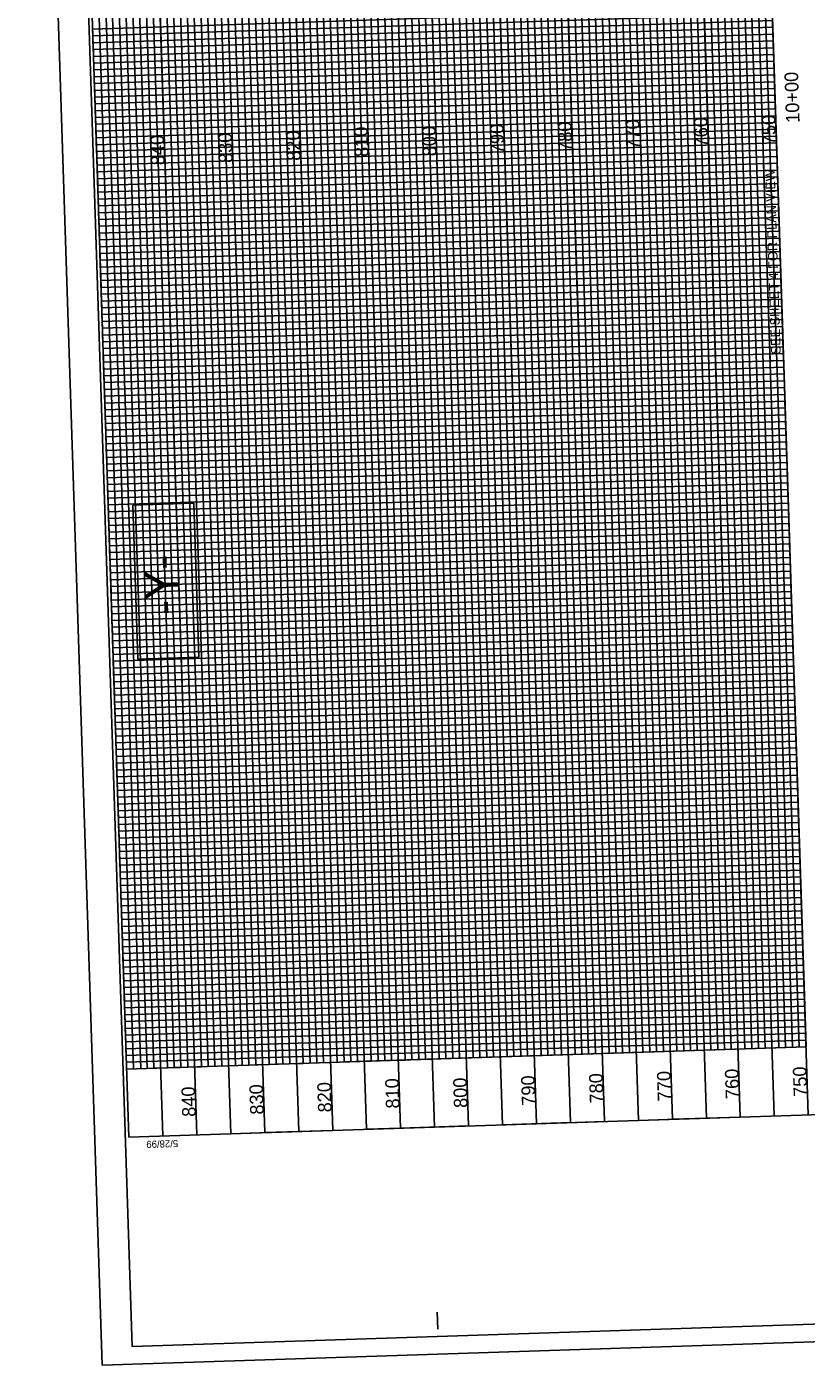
# Model space of a CAD drawing. Extents: x 1627314 to 1628469, y 762309 to 764230.
# Drawn here: x 1627314 to 1627888, y 762309 to 763293 of the extents above; entities that cross this region are included whole.
import ezdxf

# ---------------------------------------------------------------- set-up
doc = ezdxf.new("R2010")
doc.units = 0
for name, color, linetype in [('Exist Vertical Profile Horizontal Axis Label Major', 7, 'Continuous'), ('Exist Vertical Profile Vertical Axis Label', 7, 'Continuous'), ('Prop DSN Text', 7, 'Continuous'), ('Prop Grid Mask', 7, 'Continuous'), ('Sheet Data Field CELL', 7, 'Continuous'), ('Sheet DOT Grid CELL', 7, 'Continuous'), ('Sheet Layout Profile Border Port 1', 7, 'Continuous'), ('Sheet Plot Border Inside CELL', 7, 'Continuous'), ('Sheet Plot Border Outside CELL', 7, 'Continuous'), ('Sheet Profile CELL', 7, 'Continuous'), ('Sheet Profile Grid Major CELL', 7, 'Continuous'), ('Sheet Profile Grid Middle CELL', 7, 'Continuous'), ('Sheet Profile Grid Minor CELL', 7, 'Continuous')]:
    doc.layers.add(name, color=color, linetype=linetype)

msp = doc.modelspace()

# ---------------------------------------------------------------- linework, layer by layer
at = {"layer": 'Prop Grid Mask'}
for points in [[(1627366.44, 763176.67), (1627364.8, 763226.64), (1627864.53, 763242.99), (1627866.17, 763193.01)], [(1627856.17, 763192.69), (1627860.92, 763047.76), (1627870.91, 763048.09), (1627866.17, 763193.01)], [(1627440.71, 762829.99), (1627437.01, 762943.01), (1627392.29, 762941.55), (1627395.99, 762828.53)]]:
    msp.add_lwpolyline(points, close=True, dxfattribs=at)
at = {"layer": 'Sheet DOT Grid CELL'}
for p, q in [((1627590.15, 763984.41), (1627639.19, 762485.21)), ((1627640.12, 763986.05), (1627689.16, 762486.85)), ((1627690.1, 763987.68), (1627739.13, 762488.48)), ((1627740.07, 763989.32), (1627789.11, 762490.12)), ((1627790.04, 763990.95), (1627839.08, 762491.75)), ((1627396.8, 763777.93), (1627439.29, 762478.68)), ((1627446.77, 763779.57), (1627489.27, 762480.31)), ((1627496.74, 763781.25), (1627539.24, 762481.95)), ((1627546.72, 763782.83), (1627589.21, 762483.58)), ((1627862.9, 763292.96), (1627363.17, 763276.61)), ((1627864.53, 763242.99), (1627364.8, 763226.64)), ((1627866.17, 763193.01), (1627366.44, 763176.67)), ((1627867.8, 763143.04), (1627368.07, 763126.69)), ((1627869.44, 763093.07), (1627369.71, 763076.72)), ((1627871.07, 763043.09), (1627371.34, 763026.75)), ((1627872.71, 762993.12), (1627372.98, 762976.77)), ((1627874.34, 762943.15), (1627374.61, 762926.8)), ((1627875.98, 762893.17), (1627376.24, 762876.83)), ((1627877.61, 762843.2), (1627377.88, 762826.85)), ((1627879.25, 762793.23), (1627379.51, 762776.88)), ((1627880.88, 762743.25), (1627381.15, 762726.91)), ((1627882.52, 762693.28), (1627382.78, 762676.93)), ((1627884.15, 762643.31), (1627384.42, 762626.96)), ((1627885.78, 762593.33), (1627386.05, 762576.99)), ((1627887.42, 762543.36), (1627387.69, 762527.01))]:
    msp.add_line(p, q, dxfattribs=at)
at = {"layer": 'Sheet Layout Profile Border Port 1'}
msp.add_lwpolyline([(1627548.65, 762532.28), (1627887.42, 762543.36), (1627841.65, 763942.61), (1627566.8, 763933.62)], dxfattribs=at)
at = {"layer": 'Sheet Plot Border Inside CELL'}
msp.add_lwpolyline([(1628446.34, 762357.53), (1628391.86, 764023.14), (1627337.33, 763988.65), (1627391.81, 762323.04)], close=True, dxfattribs=at)
at = {"layer": 'Sheet Plot Border Outside CELL'}
msp.add_lwpolyline([(1628469.21, 762345.27), (1628413.63, 764044.37), (1627314.22, 764008.4), (1627369.79, 762309.31)], close=True, dxfattribs=at)
at = {"layer": 'Sheet Profile CELL'}
for p, q in [((1627889.05, 762493.39), (1627840.02, 763992.59)), ((1627616.56, 762335.89), (1627616.15, 762348.39))]:
    msp.add_line(p, q, dxfattribs=at)
msp.add_lwpolyline([(1627340.28, 763976.24), (1627389.32, 762477.04), (1628438.76, 762511.37), (1628389.72, 764010.57)], close=True, dxfattribs=at)
at = {"layer": 'Sheet Profile Grid Major CELL'}
for points in [[(1627546.71, 763782.88), (1627589.21, 762483.58), (1627639.19, 762485.21), (1627590.15, 763984.41)], [(1627640.12, 763986.05), (1627689.16, 762486.85), (1627739.13, 762488.48), (1627690.1, 763987.68)], [(1627740.07, 763989.32), (1627789.11, 762490.12), (1627789.11, 762490.12), (1627839.08, 762491.75), (1627790.04, 763990.95)], [(1627439.29, 762478.68), (1627396.79, 763777.98)], [(1627446.77, 763779.62), (1627489.27, 762480.31), (1627539.24, 762481.95), (1627496.74, 763781.25)], [(1627387.69, 762527.01), (1627887.42, 762543.36), (1627885.78, 762593.33), (1627386.05, 762576.99), (1627384.42, 762626.96), (1627884.15, 762643.31), (1627882.52, 762693.28), (1627382.78, 762676.93), (1627381.15, 762726.91), (1627880.88, 762743.25), (1627879.25, 762793.23), (1627379.51, 762776.88), (1627377.88, 762826.85), (1627877.61, 762843.2), (1627875.98, 762893.17), (1627376.24, 762876.83), (1627374.61, 762926.8), (1627874.34, 762943.15), (1627872.71, 762993.12), (1627372.98, 762976.77), (1627371.34, 763026.75), (1627871.07, 763043.09), (1627869.44, 763093.07), (1627369.71, 763076.72), (1627368.07, 763126.69), (1627867.8, 763143.04), (1627866.17, 763193.01), (1627366.44, 763176.67), (1627364.8, 763226.64), (1627864.53, 763242.99), (1627862.9, 763292.96), (1627363.17, 763276.61), (1627361.53, 763326.59)]]:
    msp.add_lwpolyline(points, dxfattribs=at)
at = {"layer": 'Sheet Profile Grid Middle CELL'}
msp.add_line((1627414.31, 762477.86), (1627371.81, 763777.11), dxfattribs=at)
for points in [[(1627815.03, 763991.77), (1627864.07, 762492.57)], [(1627615.14, 763985.23), (1627664.17, 762486.03), (1627714.15, 762487.67), (1627665.11, 763986.86)], [(1627715.08, 763988.5), (1627764.12, 762489.3), (1627814.09, 762490.94), (1627765.06, 763990.13)], [(1627521.73, 763782.02), (1627564.23, 762482.76), (1627614.2, 762484.4), (1627570.88, 763808.69)], [(1627421.78, 763778.8), (1627464.28, 762479.49), (1627514.25, 762481.13), (1627471.75, 763780.43)], [(1627386.87, 762552), (1627886.6, 762568.35), (1627884.97, 762618.32), (1627385.23, 762601.97), (1627383.6, 762651.95), (1627883.33, 762668.29), (1627881.7, 762718.27), (1627381.97, 762701.92), (1627380.33, 762751.89), (1627880.06, 762768.24), (1627878.43, 762818.21), (1627378.7, 762801.87), (1627377.06, 762851.84), (1627876.79, 762868.19), (1627875.16, 762918.16), (1627375.43, 762901.81), (1627373.79, 762951.79), (1627873.53, 762968.13), (1627871.89, 763018.11), (1627372.16, 763001.76), (1627370.52, 763051.73), (1627870.26, 763068.08), (1627868.62, 763118.05), (1627868.62, 763118.05), (1627368.89, 763101.71), (1627367.25, 763151.68), (1627866.99, 763168.03), (1627865.35, 763218), (1627365.62, 763201.65), (1627363.98, 763251.63), (1627863.72, 763267.97), (1627862.08, 763317.95)]]:
    msp.add_lwpolyline(points, dxfattribs=at)
at = {"layer": 'Sheet Profile Grid Minor CELL'}
for p, q in [((1627867.43, 762542.71), (1627821.66, 763941.96)), ((1627826.66, 763942.12), (1627872.43, 762542.87)), ((1627877.42, 762543.03), (1627831.66, 763942.29)), ((1627576.79, 763933.95), (1627622.56, 762534.7)), ((1627627.56, 762534.86), (1627581.79, 763934.11)), ((1627586.79, 763934.28), (1627632.56, 762535.02)), ((1627642.55, 762535.35), (1627596.78, 763934.6)), ((1627601.78, 763934.77), (1627647.55, 762535.51)), ((1627652.55, 762535.68), (1627606.78, 763934.93)), ((1627611.77, 763935.09), (1627657.54, 762535.84)), ((1627667.54, 762536.17), (1627621.77, 763935.42)), ((1627626.77, 763935.58), (1627672.53, 762536.33)), ((1627677.53, 762536.5), (1627631.76, 763935.75)), ((1627636.76, 763935.91), (1627682.53, 762536.66)), ((1627692.52, 762536.99), (1627646.75, 763936.24)), ((1627651.75, 763936.4), (1627697.52, 762537.15)), ((1627702.52, 762537.31), (1627656.75, 763936.56)), ((1627661.75, 763936.73), (1627707.52, 762537.48)), ((1627717.51, 762537.8), (1627671.74, 763937.05)), ((1627676.74, 763937.22), (1627722.51, 762537.97)), ((1627727.51, 762538.13), (1627681.74, 763937.38)), ((1627686.73, 763937.55), (1627732.5, 762538.29)), ((1627742.5, 762538.62), (1627696.73, 763937.87)), ((1627701.73, 763938.04), (1627747.49, 762538.78)), ((1627752.49, 762538.95), (1627706.72, 763938.2)), ((1627711.72, 763938.36), (1627757.49, 762539.11)), ((1627767.48, 762539.44), (1627721.71, 763938.69)), ((1627726.71, 763938.85), (1627772.48, 762539.6)), ((1627731.71, 763939.02), (1627777.48, 762539.76)), ((1627736.71, 763939.18), (1627782.48, 762539.93)), ((1627792.47, 762540.25), (1627746.7, 763939.51)), ((1627751.7, 763939.67), (1627797.47, 762540.42)), ((1627802.47, 762540.58), (1627756.7, 763939.83)), ((1627761.69, 763940), (1627807.46, 762540.75)), ((1627817.46, 762541.07), (1627771.69, 763940.32)), ((1627776.69, 763940.49), (1627822.45, 762541.24)), ((1627827.45, 762541.4), (1627781.68, 763940.65)), ((1627786.68, 763940.81), (1627832.45, 762541.56)), ((1627842.44, 762541.89), (1627796.67, 763941.14)), ((1627801.67, 763941.3), (1627847.44, 762542.05)), ((1627852.44, 762542.22), (1627806.67, 763941.47)), ((1627811.67, 763941.63), (1627857.44, 762542.38)), ((1627392.68, 762527.18), (1627351.82, 763776.51)), ((1627356.82, 763776.67), (1627398.03, 762527.35)), ((1627402.68, 762527.5), (1627361.81, 763776.84)), ((1627481.75, 763780.71), (1627522.61, 762531.43)), ((1627486.75, 763780.92), (1627527.61, 762531.59)), ((1627491.74, 763781.09), (1627532.61, 762531.75)), ((1627542.6, 762532.08), (1627501.74, 763781.41)), ((1627506.74, 763781.58), (1627547.6, 762532.25)), ((1627552.6, 762532.41), (1627511.73, 763781.69)), ((1627531.72, 763782.34), (1627572.59, 762533.06)), ((1627577.59, 762533.23), (1627536.72, 763782.51)), ((1627556.71, 763783.16), (1627597.57, 762533.88)), ((1627602.57, 762534.04), (1627561.71, 763783.33)), ((1627397.68, 762527.34), (1627397.68, 762527.34))]:
    msp.add_line(p, q, dxfattribs=at)
for points in [[(1627836.65, 763942.45), (1627882.42, 762543.2)], [(1627566.71, 763783.49), (1627607.57, 762534.21), (1627617.56, 762534.53), (1627571.79, 763933.79)], [(1627366.81, 763777), (1627407.68, 762527.67), (1627417.67, 762528), (1627376.81, 763777.33)], [(1627381.8, 763777.44), (1627422.67, 762528.16), (1627427.67, 762528.32), (1627386.8, 763777.65)], [(1627391.8, 763777.82), (1627432.66, 762528.49), (1627442.66, 762528.81), (1627401.79, 763778.14)], [(1627406.79, 763778.31), (1627447.65, 762528.98), (1627452.65, 762529.14), (1627411.79, 763778.47)], [(1627416.78, 763778.63), (1627457.65, 762529.3), (1627467.64, 762529.63), (1627426.78, 763778.96)], [(1627431.78, 763779.13), (1627472.64, 762529.79), (1627477.64, 762529.96), (1627436.77, 763779.29)], [(1627441.77, 763779.45), (1627482.64, 762530.12), (1627492.63, 762530.45), (1627451.77, 763779.78)], [(1627456.86, 763779.95), (1627497.72, 762530.71), (1627502.62, 762530.87), (1627461.76, 763780.11)], [(1627466.76, 763780.27), (1627507.62, 762530.94), (1627517.62, 762531.26), (1627476.75, 763780.6)], [(1627516.73, 763781.85), (1627557.6, 762532.57), (1627567.59, 762532.9), (1627526.73, 763782.18)], [(1627541.72, 763782.67), (1627582.58, 762533.39), (1627592.58, 762533.72), (1627551.71, 763783)], [(1627862.57, 763302.95), (1627362.84, 763286.61), (1627362.68, 763291.61), (1627862.41, 763307.95)], [(1627370.36, 763056.73), (1627870.09, 763073.08), (1627869.93, 763078.07), (1627370.2, 763061.73), (1627370.03, 763066.73), (1627869.77, 763083.07), (1627869.6, 763088.07), (1627369.87, 763071.72), (1627369.54, 763081.72), (1627869.28, 763098.06), (1627869.11, 763103.06), (1627369.38, 763086.72), (1627369.22, 763091.71), (1627868.95, 763108.06), (1627868.78, 763113.06), (1627369.05, 763096.71), (1627368.73, 763106.7), (1627868.46, 763123.05), (1627868.29, 763128.05), (1627368.56, 763111.7), (1627368.4, 763116.7), (1627868.13, 763133.05), (1627867.97, 763138.04), (1627368.23, 763121.7), (1627367.91, 763131.69), (1627867.64, 763148.04), (1627867.48, 763153.03), (1627367.74, 763136.69), (1627367.58, 763141.69), (1627867.31, 763158.03), (1627867.15, 763163.03), (1627367.42, 763146.68), (1627367.09, 763156.68), (1627866.82, 763173.02), (1627866.66, 763178.02), (1627366.93, 763161.68), (1627366.76, 763166.67), (1627866.5, 763183.02), (1627866.33, 763188.02), (1627366.6, 763171.67), (1627366.27, 763181.66), (1627866.01, 763198.01), (1627866.01, 763198.01), (1627865.84, 763203.01), (1627366.11, 763186.66), (1627365.95, 763191.66), (1627865.68, 763208.01), (1627865.52, 763213), (1627365.78, 763196.66), (1627365.46, 763206.65), (1627865.19, 763223), (1627865.03, 763227.99), (1627365.29, 763211.65), (1627365.13, 763216.65), (1627864.86, 763232.99), (1627864.7, 763237.99), (1627364.97, 763221.64), (1627364.64, 763231.64), (1627864.37, 763247.98), (1627864.21, 763252.98), (1627364.48, 763236.63), (1627364.31, 763241.63), (1627864.04, 763257.98), (1627863.88, 763262.98), (1627364.15, 763246.63), (1627363.82, 763256.62), (1627863.55, 763272.97), (1627863.39, 763277.97), (1627363.66, 763261.62), (1627363.49, 763266.62), (1627863.23, 763282.97), (1627863.06, 763287.96), (1627363.33, 763271.62), (1627363, 763281.61), (1627862.74, 763297.96)], [(1627880.39, 762758.25), (1627880.23, 762763.24), (1627380.49, 762746.9), (1627380.17, 762756.89), (1627879.9, 762773.24), (1627879.74, 762778.24), (1627380, 762761.89), (1627379.84, 762766.89), (1627879.57, 762783.23), (1627879.41, 762788.23), (1627379.68, 762771.88), (1627379.35, 762781.88), (1627879.08, 762798.22), (1627878.92, 762803.22), (1627379.19, 762786.88), (1627379.02, 762791.87), (1627878.76, 762808.22), (1627878.59, 762813.22), (1627378.86, 762796.87), (1627378.53, 762806.86), (1627878.27, 762823.21), (1627878.1, 762828.21), (1627378.37, 762811.86), (1627378.21, 762816.86), (1627877.94, 762833.21), (1627877.78, 762838.2), (1627378.04, 762821.86), (1627377.72, 762831.85), (1627877.45, 762848.2), (1627877.28, 762853.19), (1627377.55, 762836.85), (1627377.39, 762841.85), (1627877.12, 762858.19), (1627876.96, 762863.19), (1627377.23, 762846.84), (1627376.9, 762856.84), (1627876.63, 762873.18), (1627876.47, 762878.18), (1627376.73, 762861.84), (1627376.57, 762866.83), (1627876.3, 762883.18), (1627876.14, 762888.18), (1627376.41, 762871.83), (1627376.08, 762881.82), (1627875.81, 762898.17), (1627875.65, 762903.17), (1627375.92, 762886.82), (1627375.75, 762891.82), (1627875.49, 762908.17), (1627875.32, 762913.16), (1627375.59, 762896.82), (1627375.26, 762906.81), (1627875, 762923.16), (1627874.83, 762928.15), (1627375.1, 762911.81), (1627374.94, 762916.81), (1627874.67, 762933.15), (1627874.51, 762938.15), (1627374.77, 762921.8), (1627374.45, 762931.8), (1627874.18, 762948.14), (1627874.02, 762953.14), (1627374.28, 762936.8), (1627374.12, 762941.79), (1627873.85, 762958.14), (1627873.69, 762963.14), (1627373.96, 762946.79), (1627373.63, 762956.78), (1627873.36, 762973.13), (1627873.2, 762978.13), (1627373.47, 762961.78), (1627373.3, 762966.78), (1627873.03, 762983.13), (1627872.87, 762988.12), (1627373.14, 762971.78), (1627372.81, 762981.77), (1627872.54, 762998.12), (1627872.38, 763003.11), (1627372.65, 762986.77), (1627372.48, 762991.77), (1627872.22, 763008.11), (1627872.05, 763013.11), (1627372.32, 762996.76), (1627371.99, 763006.76), (1627871.73, 763023.1), (1627871.56, 763028.1), (1627371.83, 763011.76), (1627371.67, 763016.75), (1627871.4, 763033.1), (1627871.24, 763038.1), (1627371.5, 763021.75), (1627371.18, 763031.74), (1627870.91, 763048.09), (1627870.75, 763053.09), (1627371.01, 763036.74), (1627370.85, 763041.74), (1627870.58, 763058.09), (1627870.42, 763063.08), (1627370.69, 763046.74), (1627370.36, 763056.73)], [(1627387.52, 762532.01), (1627887.26, 762548.36), (1627887.09, 762553.36), (1627387.36, 762537.01), (1627387.2, 762542.01), (1627886.93, 762558.35), (1627886.77, 762563.35), (1627387.03, 762547), (1627386.71, 762557), (1627886.44, 762573.34), (1627886.28, 762578.34), (1627386.54, 762562), (1627386.38, 762566.99), (1627886.11, 762583.34), (1627885.95, 762588.34), (1627885.62, 762598.33), (1627885.46, 762603.33), (1627385.73, 762586.98), (1627385.56, 762591.98), (1627885.29, 762608.33), (1627885.13, 762613.32), (1627385.4, 762596.98), (1627385.07, 762606.97), (1627884.8, 762623.32), (1627884.64, 762628.32), (1627384.91, 762611.97), (1627384.74, 762616.97), (1627884.48, 762633.31), (1627884.31, 762638.31), (1627384.58, 762621.96), (1627384.25, 762631.96), (1627883.99, 762648.3), (1627883.82, 762653.3), (1627384.09, 762636.96), (1627383.93, 762641.95), (1627883.66, 762658.3), (1627883.5, 762663.3), (1627383.76, 762646.95), (1627383.44, 762656.95), (1627883.17, 762673.29), (1627883.01, 762678.29), (1627383.27, 762661.94), (1627383.11, 762666.94), (1627882.84, 762683.29), (1627882.68, 762688.28), (1627382.95, 762671.94), (1627382.62, 762681.93), (1627882.35, 762698.28), (1627882.19, 762703.28), (1627382.46, 762686.93), (1627382.29, 762691.93), (1627882.03, 762708.27), (1627881.86, 762713.27), (1627382.13, 762696.92), (1627381.8, 762706.92), (1627881.53, 762723.26), (1627881.37, 762728.26), (1627381.64, 762711.92), (1627381.48, 762716.91), (1627881.21, 762733.26), (1627881.04, 762738.26), (1627381.31, 762721.91), (1627380.98, 762731.9), (1627880.72, 762748.25), (1627880.55, 762753.25), (1627380.82, 762736.9), (1627380.66, 762741.9), (1627880.39, 762758.25)], [(1627885.95, 762588.34), (1627386.22, 762571.99), (1627385.89, 762581.99), (1627885.62, 762598.33)]]:
    msp.add_lwpolyline(points, dxfattribs=at)

# ---------------------------------------------------------------- texts
at = {"layer": 'Exist Vertical Profile Horizontal Axis Label Major'}
msp.add_text('10+00', height=10, rotation=91.87347, dxfattribs=at).set_placement((1627882.7, 763222.88))
at = {"layer": 'Exist Vertical Profile Vertical Axis Label'}
for s, p in [('770', (1627765.53, 763203.16)), ('760', (1627815.51, 763204.8)), ('750', (1627865.48, 763206.43)), ('830', (1627465.69, 763193.35)), ('820', (1627515.67, 763194.99)), ('810', (1627565.6, 763197.82)), ('800', (1627615.61, 763198.26)), ('790', (1627665.59, 763199.89)), ('780', (1627715.56, 763201.53)), ('840', (1627415.72, 763191.72)), ('770', (1627788.42, 762503.53)), ('760', (1627838.39, 762505.17)), ('750', (1627888.37, 762506.8)), ('830', (1627488.58, 762493.73)), ('820', (1627538.55, 762495.36)), ('810', (1627588.49, 762498.19)), ('800', (1627638.5, 762498.63)), ('790', (1627688.47, 762500.27)), ('780', (1627738.45, 762501.9)), ('840', (1627438.61, 762492.09))]:
    msp.add_text(s, height=10, rotation=91.87347, dxfattribs=at).set_placement(p)
at = {"layer": 'Prop DSN Text'}
msp.add_text('SEE SHEET 4 FOR PLAN VIEW', height=7, rotation=91.87347, dxfattribs=at).set_placement((1627868.81, 763052.61))
at = {"layer": 'Sheet Data Field CELL'}
msp.add_text('-Y-', height=25, rotation=91.87347, dxfattribs=at).set_placement((1627426.63, 762861.15))
at = {"layer": 'Sheet Profile CELL'}
msp.add_text('5/28/99', height=5.25, rotation=181.87347, dxfattribs=at).set_placement((1627425.5, 762474.99))

doc.saveas('drawing.dxf')
